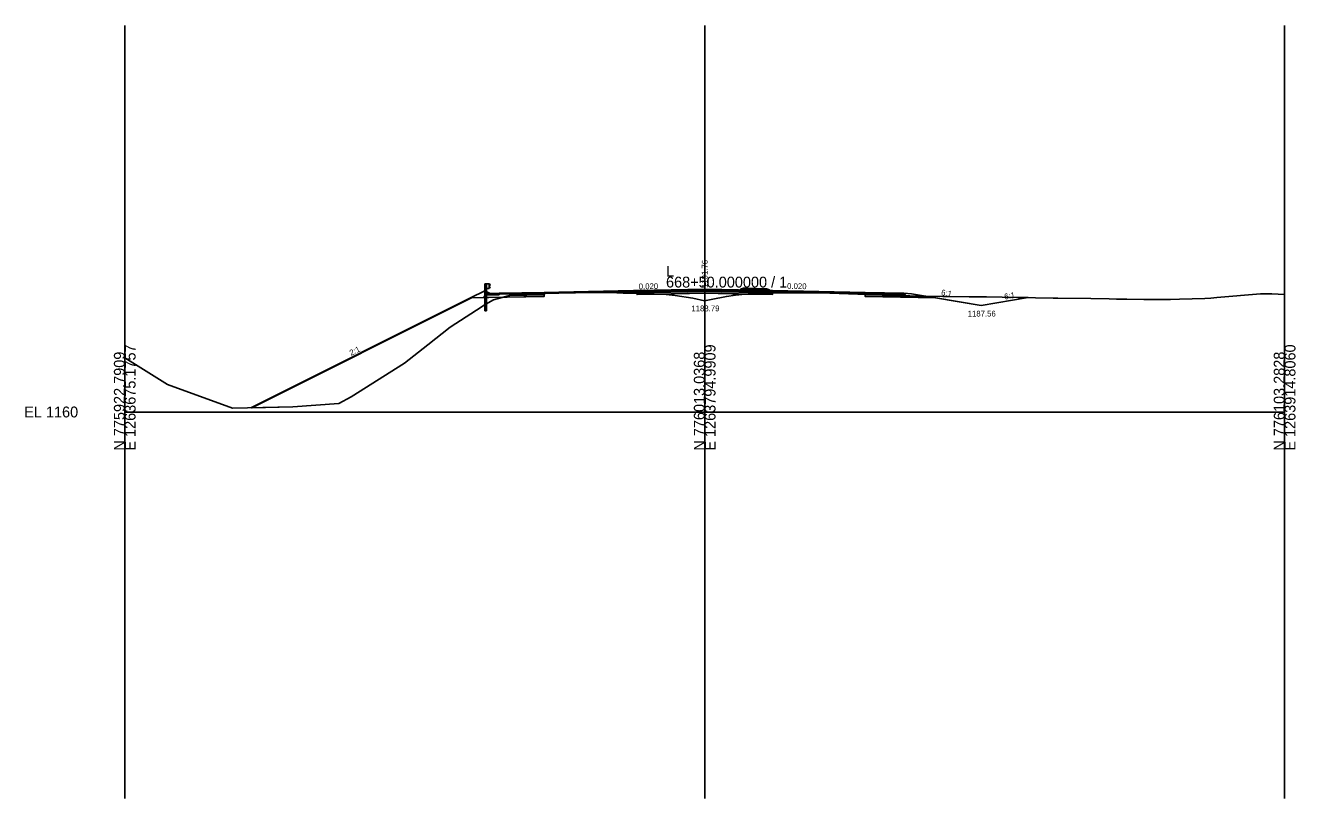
# Model space of a CAD drawing. Extents: x -41 to 1262860, y -100 to 777489.
# Drawn here: x -25.7 to 302.8, y 2655 to 2855 of the extents above; entities that cross this region are included whole.
import ezdxf

# ---------------------------------------------------------------- set-up
doc = ezdxf.new("R2010")
doc.units = 0
for name, color, linetype in [('Exist Cross Section Cell', 7, 'Continuous'), ('Exist XS Center Line Elevation Label', 7, 'Continuous'), ('Exist XS Ground Line', 7, 'Continuous'), ('Prop CMT Guardrail Graphics', 7, 'Continuous'), ('Prop CMT Pvmt Course 1', 7, 'Continuous'), ('Prop CMT Pvmt Course 4', 7, 'Continuous'), ('Prop CMT Pvmt Surface', 7, 'Continuous'), ('Prop CMT Shld Paved Course 1', 7, 'Continuous'), ('Prop CMT Shld Paved Course 2', 7, 'Continuous'), ('Prop CMT Shld Paved Course 4', 7, 'Continuous'), ('Prop CMT Slope Grass', 7, 'Continuous'), ('Prop CMT Subgrade Earthwork', 7, 'Continuous'), ('Prop Conc Curb and Gutter', 7, 'Continuous'), ('Prop Conc Island Cover', 7, 'Continuous'), ('Prop XS Ditch Standard Text', 7, 'Continuous'), ('Prop XS Earthwork Shape', 7, 'Continuous'), ('Prop XS Exc Vertical Line 1', 7, 'Continuous'), ('Prop XS Exc Vertical Line 2', 7, 'Continuous'), ('Prop XS Exc Vertical Line 3', 7, 'Continuous'), ('Prop XS Finish Grade', 7, 'Continuous'), ('Prop XS Hydro Elevations', 7, 'Continuous'), ('Prop XS SE Text', 7, 'Continuous'), ('Prop XS Side Slope Text', 7, 'Continuous'), ('Scratch_Level_4', 7, 'Continuous'), ('Scratch_Level_6', 7, 'Continuous'), ('Typical Curb CELL', 7, 'Continuous')]:
    doc.layers.add(name, color=color, linetype=linetype)

msp = doc.modelspace()

# ---------------------------------------------------------------- linework, layer by layer
at = {"layer": 'Exist Cross Section Cell'}
for p, q in [((150, 2755), (150, 2790)), ((0, 2755), (150, 2755)), ((150, 2755), (300, 2755))]:
    msp.add_line(p, q, dxfattribs=at)
at = {"layer": 'Exist XS Ground Line'}
msp.add_lwpolyline([(0, 2769.05), (11.1, 2762.1), (27.86, 2756), (43.47, 2756.32), (55.34, 2757.21), (58.55, 2758.95), (72.33, 2767.67), (78.38, 2772.37), (84.21, 2776.97), (90.99, 2781.31), (91.43, 2781.64), (92.75, 2782.52), (95.38, 2783.98), (98.24, 2784.76), (100.15, 2785.3), (103.76, 2785.44), (107.51, 2785.65), (108.83, 2785.7), (111.35, 2785.8), (120.48, 2785.88), (123.71, 2785.9), (130.82, 2785.71), (136.05, 2785.56), (138.7, 2785.46), (139.23, 2785.44), (142.37, 2785.16), (146.9, 2784.46), (149.94, 2783.78), (151.72, 2784.13), (155.64, 2784.91), (157.93, 2785.23), (161.25, 2785.6), (162.83, 2785.67), (164.85, 2785.76), (172.04, 2785.82), (177.25, 2785.86), (182.4, 2785.74), (189.6, 2785.52), (192.84, 2785.36), (194.13, 2785.3), (195.95, 2785.18), (197.83, 2785.03), (202.54, 2785.06), (203.07, 2785.05), (204.73, 2784.99), (218.4, 2784.82), (222.88, 2784.77), (231, 2784.65), (240.17, 2784.45), (240.71, 2784.44), (241.35, 2784.43), (249.91, 2784.33), (254.58, 2784.23), (256.5, 2784.15), (259.18, 2784.15), (263.55, 2784.06), (270.45, 2784.14), (272.8, 2784.19), (279.39, 2784.36), (280.89, 2784.45), (282.46, 2784.63), (293.74, 2785.53), (296.69, 2785.59), (300, 2785.41)], dxfattribs=at)
at = {"layer": 'Prop CMT Guardrail Graphics'}
for p, q in [((93.11, 2788.16), (93.59, 2788.16)), ((93.11, 2785.66), (93.11, 2788.16)), ((93.59, 2786.98), (93.59, 2788.16)), ((93.59, 2788.16), (94.26, 2788.16)), ((93.59, 2788.16), (93.59, 2785.65)), ((94.26, 2786.98), (93.59, 2786.98)), ((94.26, 2788.16), (94.26, 2786.98)), ((94.26, 2788.08), (94.26, 2787.06)), ((94.36, 2788.06), (94.26, 2788.08)), ((94.26, 2787.06), (94.36, 2787.08)), ((94.27, 2787.62), (94.5, 2787.82)), ((94.27, 2787.53), (94.27, 2787.62)), ((94.5, 2787.33), (94.27, 2787.53)), ((94.5, 2787.96), (94.36, 2788.06)), ((94.36, 2787.08), (94.5, 2787.18)), ((94.5, 2787.82), (94.5, 2787.96)), ((94.5, 2787.18), (94.5, 2787.33)), ((93.11, 2781.16), (93.11, 2785.66)), ((93.59, 2785.65), (93.59, 2781.16)), ((93.59, 2781.16), (93.11, 2781.16))]:
    msp.add_line(p, q, dxfattribs=at)
at = {"layer": 'Prop CMT Pvmt Course 1'}
for p, q in [((132.5, 2786.16), (150, 2786.51)), ((150, 2786.51), (167.49, 2786.16))]:
    msp.add_line(p, q, dxfattribs=at)
for points in [[(108.5, 2785.68), (108.5, 2785.93), (127.66, 2786.32), (127.66, 2786.32), (131.63, 2786.39), (131.63, 2786.39), (131.66, 2786.4), (131.69, 2786.4), (131.72, 2786.4), (131.75, 2786.4), (131.78, 2786.4), (131.79, 2786.4), (131.79, 2786.4), (132.5, 2786.41), (132.5, 2786.16), (132.5, 2786.16), (131.79, 2786.15), (131.79, 2786.15), (131.78, 2786.15), (131.75, 2786.15), (131.72, 2786.15), (131.69, 2786.15), (131.66, 2786.15), (131.63, 2786.14), (131.63, 2786.14), (127.66, 2786.07), (127.66, 2786.07), (108.5, 2785.68), (108.5, 2785.68)], [(191.5, 2785.68), (191.5, 2785.93), (191.5, 2785.93), (167.5, 2786.41), (167.5, 2786.16), (167.5, 2786.16), (191.5, 2785.68), (191.5, 2785.68), (191.5, 2785.68)]]:
    msp.add_lwpolyline(points, dxfattribs=at)
at = {"layer": 'Prop CMT Pvmt Course 4'}
for p, q in [((108.5, 2784.89), (93.44, 2784.59)), ((132.5, 2785.83), (132.5, 2785.37)), ((132.5, 2785.37), (150, 2785.72)), ((150, 2785.72), (167.5, 2785.37)), ((167.5, 2785.83), (167.5, 2785.37)), ((191.5, 2784.89), (202.56, 2784.67)), ((202.1, 2785.14), (202.56, 2784.67))]:
    msp.add_line(p, q, dxfattribs=at)
at = {"layer": 'Prop CMT Pvmt Surface'}
for p, q in [((108.5, 2785.93), (132.5, 2786.41)), ((132.5, 2786.41), (150, 2786.76)), ((150, 2786.76), (167.5, 2786.41)), ((167.5, 2786.41), (191.5, 2785.93)), ((96.85, 2785.7), (108.5, 2785.93)), ((191.5, 2785.93), (201.5, 2785.73))]:
    msp.add_line(p, q, dxfattribs=at)
at = {"layer": 'Prop CMT Shld Paved Course 1'}
for p, q in [((132.5, 2786.41), (150, 2786.76)), ((150, 2786.76), (167.5, 2786.41)), ((94.5, 2785.65), (108.5, 2785.93)), ((108.5, 2785.68), (96.85, 2785.45)), ((104.5, 2785.85), (104.5, 2785.85)), ((108.5, 2785.93), (108.5, 2785.68)), ((108.5, 2785.68), (108.5, 2785.68)), ((191.5, 2785.93), (191.5, 2785.68)), ((191.5, 2785.93), (201.5, 2785.73)), ((191.5, 2785.68), (191.5, 2785.68)), ((191.5, 2785.68), (201.76, 2785.48)), ((201.76, 2785.48), (201.5, 2785.73))]:
    msp.add_line(p, q, dxfattribs=at)
at = {"layer": 'Prop CMT Shld Paved Course 2'}
for p, q in [((120.48, 2785.92), (123.71, 2785.99)), ((123.71, 2785.99), (127.66, 2786.07)), ((123.71, 2785.99), (123.71, 2785.99)), ((123.71, 2785.99), (123.71, 2785.99)), ((127.66, 2786.07), (130.82, 2786.13)), ((127.66, 2786.07), (127.66, 2786.07)), ((130.82, 2786.13), (131.63, 2786.14)), ((130.82, 2786.13), (130.82, 2786.13)), ((131.63, 2786.14), (132.5, 2786.16)), ((132.5, 2785.83), (150, 2786.18)), ((132.5, 2786.16), (132.5, 2786.16)), ((132.5, 2786.16), (132.5, 2785.83)), ((150, 2786.18), (167.5, 2785.83)), ((167.5, 2785.83), (167.5, 2786.16)), ((167.5, 2786.16), (172.04, 2786.07)), ((172.04, 2786.07), (172.04, 2786.07)), ((172.04, 2786.07), (177.25, 2785.97)), ((177.25, 2785.97), (177.25, 2785.97)), ((177.25, 2785.97), (177.25, 2785.97)), ((177.25, 2785.97), (182.4, 2785.86)), ((108.5, 2785.35), (99.64, 2785.17)), ((103.9, 2785.26), (103.9, 2785.26)), ((103.9, 2785.26), (103.9, 2785.26)), ((103.9, 2785.26), (103.9, 2785.26)), ((103.9, 2785.26), (103.9, 2785.26)), ((103.9, 2785.26), (103.9, 2785.26)), ((103.9, 2785.26), (103.9, 2785.26)), ((103.9, 2785.26), (103.9, 2785.26)), ((103.9, 2785.26), (103.9, 2785.26)), ((108.5, 2785.68), (108.83, 2785.69)), ((108.83, 2785.69), (108.5, 2785.68)), ((108.5, 2785.68), (108.5, 2785.35)), ((108.5, 2785.35), (108.5, 2785.35)), ((108.83, 2785.69), (111.35, 2785.74)), ((111.35, 2785.74), (108.83, 2785.69)), ((108.83, 2785.69), (108.83, 2785.69)), ((108.83, 2785.69), (108.83, 2785.69)), ((111.35, 2785.74), (120.48, 2785.92)), ((116.62, 2785.84), (111.35, 2785.74)), ((111.35, 2785.74), (111.35, 2785.74)), ((120.48, 2785.88), (116.62, 2785.84)), ((120.48, 2785.92), (120.48, 2785.92)), ((123.71, 2785.9), (120.48, 2785.88)), ((120.48, 2785.88), (120.48, 2785.88)), ((127.66, 2785.79), (123.71, 2785.9)), ((123.71, 2785.9), (123.71, 2785.9)), ((123.71, 2785.9), (123.71, 2785.9)), ((128.94, 2785.76), (127.66, 2785.79)), ((127.66, 2785.79), (127.66, 2785.79)), ((132.5, 2785.83), (128.94, 2785.76)), ((128.94, 2785.76), (128.94, 2785.76)), ((132.5, 2785.83), (132.5, 2785.83)), ((132.5, 2785.83), (132.5, 2785.83)), ((169.01, 2785.8), (167.5, 2785.83)), ((167.5, 2785.83), (167.5, 2785.83)), ((172.04, 2785.82), (169.01, 2785.8)), ((169.01, 2785.8), (169.01, 2785.8)), ((177.25, 2785.86), (172.04, 2785.82)), ((172.04, 2785.82), (172.04, 2785.82)), ((182.4, 2785.74), (177.25, 2785.86)), ((177.25, 2785.86), (177.25, 2785.86)), ((177.25, 2785.86), (177.25, 2785.86)), ((182.4, 2785.86), (182.4, 2785.86)), ((182.4, 2785.86), (189.6, 2785.72)), ((189.6, 2785.52), (182.4, 2785.74)), ((182.4, 2785.74), (182.4, 2785.74)), ((189.6, 2785.72), (191.5, 2785.68)), ((191.5, 2785.42), (189.6, 2785.52)), ((191.5, 2785.68), (191.5, 2785.35)), ((191.5, 2785.68), (191.5, 2785.68)), ((191.5, 2785.68), (191.5, 2785.42)), ((191.5, 2785.42), (191.5, 2785.42)), ((191.5, 2785.42), (191.5, 2785.42)), ((191.5, 2785.35), (191.5, 2785.35)), ((191.5, 2785.35), (202.1, 2785.14)), ((202.1, 2785.14), (201.76, 2785.48))]:
    msp.add_line(p, q, dxfattribs=at)
at = {"layer": 'Prop CMT Shld Paved Course 4'}
for p, q in [((92.58, 2784.57), (93.32, 2785.31)), ((93.32, 2785.31), (93.83, 2785.31)), ((103.9, 2785.26), (103.9, 2785.26)), ((103.9, 2785.26), (103.9, 2785.26)), ((103.9, 2785.26), (103.9, 2785.26)), ((103.9, 2785.26), (103.9, 2785.26)), ((108.5, 2785.35), (108.5, 2784.89)), ((128.94, 2785.76), (132.5, 2785.66)), ((169.01, 2785.8), (167.5, 2785.79)), ((191.5, 2785.35), (191.5, 2784.89))]:
    msp.add_line(p, q, dxfattribs=at)
at = {"layer": 'Prop CMT Slope Grass'}
for q in [(89.47, 2784.51), (93.83, 2785.99)]:
    msp.add_line((93.14, 2786.34), q, dxfattribs=at)
at = {"layer": 'Prop CMT Subgrade Earthwork'}
for p, q in [((108.5, 2784.89), (89.47, 2784.51)), ((108.5, 2784.89), (108.5, 2785.69)), ((150, 2785.72), (132.5, 2785.37)), ((132.5, 2785.37), (132.5, 2785.66)), ((167.5, 2785.37), (150, 2785.72)), ((167.5, 2785.79), (167.5, 2785.37)), ((191.5, 2784.89), (191.5, 2785.42)), ((191.5, 2784.89), (209.78, 2784.52))]:
    msp.add_line(p, q, dxfattribs=at)
at = {"layer": 'Prop Conc Curb and Gutter'}
for p, q in [((159.25, 2786.58), (159.26, 2786.74)), ((159.25, 2786.58), (159.25, 2786.58)), ((159.25, 2786.58), (159.25, 2786.45)), ((161.01, 2786.58), (159.25, 2786.58)), ((159.25, 2786.58), (159.25, 2786.58)), ((159.25, 2786.45), (159.25, 2786.45)), ((159.25, 2786.45), (161.01, 2786.45)), ((159.26, 2786.74), (160.01, 2786.99)), ((159.26, 2786.74), (159.26, 2786.74)), ((160.01, 2786.99), (161.01, 2787.01)), ((160.01, 2786.99), (160.01, 2786.99)), ((161.01, 2787.01), (161.01, 2786.58)), ((161.01, 2786.45), (161.01, 2786.58)), ((161.01, 2786.58), (161.01, 2786.58)), ((161.01, 2786.45), (161.01, 2786.45)), ((161.01, 2786.45), (161.01, 2786.45)), ((165.99, 2786.84), (164.99, 2786.86)), ((164.99, 2786.86), (164.99, 2786.43)), ((166.75, 2786.43), (164.99, 2786.43)), ((164.99, 2786.43), (164.99, 2786.3)), ((164.99, 2786.43), (164.99, 2786.43)), ((164.99, 2786.3), (164.99, 2786.3)), ((164.99, 2786.3), (166.75, 2786.3)), ((166.74, 2786.59), (165.99, 2786.84)), ((165.99, 2786.84), (165.99, 2786.84)), ((166.75, 2786.43), (166.74, 2786.59)), ((166.74, 2786.59), (166.74, 2786.59)), ((166.75, 2786.3), (166.75, 2786.43)), ((166.75, 2786.43), (166.75, 2786.43)), ((166.75, 2786.43), (166.75, 2786.43)), ((166.75, 2786.3), (166.75, 2786.3)), ((166.75, 2786.3), (166.75, 2786.3))]:
    msp.add_line(p, q, dxfattribs=at)
at = {"layer": 'Prop Conc Island Cover'}
for p, q in [((161.01, 2787.01), (161.01, 2786.76)), ((161.01, 2787.01), (164.99, 2786.86)), ((161.01, 2786.76), (164.99, 2786.61)), ((164.99, 2786.61), (164.99, 2786.86)), ((164.99, 2786.86), (164.99, 2786.86)), ((164.99, 2786.61), (164.99, 2786.61))]:
    msp.add_line(p, q, dxfattribs=at)
at = {"layer": 'Prop XS Earthwork Shape'}
for points in [[(78.38, 2772.37), (84.21, 2776.97), (90.99, 2781.31), (91.43, 2781.64), (92.75, 2782.52), (95.38, 2783.98), (97.94, 2784.68), (93.44, 2784.59), (89.7, 2784.51), (32.87, 2756.1), (43.47, 2756.32), (55.34, 2757.21), (58.55, 2758.95), (72.33, 2767.67)], [(103.76, 2785.44), (107.51, 2785.65), (108.5, 2785.69), (108.5, 2784.89), (97.94, 2784.68), (98.24, 2784.76), (100.15, 2785.3)], [(132.5, 2785.66), (136.05, 2785.56), (138.11, 2785.48), (132.5, 2785.37)], [(146.9, 2784.46), (149.94, 2783.78), (151.72, 2784.13), (155.64, 2784.91), (157.93, 2785.23), (160.45, 2785.51), (150, 2785.72), (138.11, 2785.48), (138.7, 2785.46), (139.23, 2785.44), (142.37, 2785.16)], [(164.85, 2785.76), (167.5, 2785.79), (167.5, 2785.37), (160.45, 2785.51), (161.25, 2785.6), (162.83, 2785.67)], [(195.95, 2785.18), (197.83, 2785.03), (202.18, 2785.06), (202.56, 2784.67), (191.5, 2784.89), (191.5, 2785.42), (192.84, 2785.36), (194.13, 2785.3)], [(202.54, 2785.06), (203.07, 2785.05), (204.73, 2784.99), (207.2, 2784.96), (209.78, 2784.52), (202.56, 2784.67), (202.18, 2785.06)], [(221.5, 2782.57), (233.63, 2784.59), (231, 2784.65), (222.88, 2784.77), (218.4, 2784.82), (207.2, 2784.96), (209.78, 2784.52)]]:
    msp.add_lwpolyline(points, close=True, dxfattribs=at)
at = {"layer": 'Prop XS Exc Vertical Line 1'}
msp.add_line((0, 2655), (0, 2855), dxfattribs=at)
at = {"layer": 'Prop XS Exc Vertical Line 2'}
msp.add_line((150, 2655), (150, 2855), dxfattribs=at)
at = {"layer": 'Prop XS Exc Vertical Line 3'}
msp.add_line((300, 2655), (300, 2855), dxfattribs=at)
at = {"layer": 'Prop XS Finish Grade'}
for p, q in [((89.47, 2784.51), (32.64, 2756.09)), ((201.5, 2785.73), (203.5, 2785.57)), ((201.5, 2785.73), (202.56, 2784.67)), ((203.5, 2785.57), (221.5, 2782.57)), ((221.5, 2782.57), (233.63, 2784.59))]:
    msp.add_line(p, q, dxfattribs=at)
at = {"layer": 'Scratch_Level_4'}
msp.add_line((300, 2655), (300, 2855), dxfattribs=at)
at = {"layer": 'Scratch_Level_6'}
msp.add_line((0, 2655), (0, 2855), dxfattribs=at)
at = {"layer": 'Typical Curb CELL'}
for p, q in [((93.83, 2785.31), (93.83, 2785.99)), ((94.52, 2785.64), (93.83, 2785.99)), ((93.83, 2785.31), (96.85, 2785.28)), ((93.87, 2785.61), (94.02, 2785.65)), ((94, 2785.56), (93.87, 2785.61)), ((94.02, 2785.65), (94, 2785.56)), ((94.54, 2785.52), (94.43, 2785.45)), ((94.43, 2785.45), (94.6, 2785.41)), ((96.84, 2785.7), (94.52, 2785.64)), ((94.6, 2785.41), (94.54, 2785.52)), ((95.28, 2785.57), (95.24, 2785.46)), ((95.24, 2785.46), (95.36, 2785.45)), ((95.36, 2785.45), (95.28, 2785.57)), ((95.78, 2785.51), (95.68, 2785.43)), ((95.68, 2785.43), (95.85, 2785.39)), ((95.85, 2785.39), (95.78, 2785.51)), ((96.53, 2785.56), (96.49, 2785.44)), ((96.49, 2785.44), (96.61, 2785.44)), ((96.61, 2785.44), (96.53, 2785.56)), ((96.85, 2785.7), (96.85, 2785.7)), ((96.85, 2785.28), (96.85, 2785.69))]:
    msp.add_line(p, q, dxfattribs=at)
for centre in [(93.9, 2785.7), (93.99, 2785.42), (94.11, 2785.47), (94.37, 2785.5), (94.38, 2785.45), (94.56, 2785.36), (94.59, 2785.46), (94.78, 2785.42), (94.83, 2785.54), (94.96, 2785.51), (94.99, 2785.38), (95.05, 2785.41), (95.24, 2785.41), (95.36, 2785.46), (95.45, 2785.45), (95.55, 2785.4), (95.61, 2785.54), (95.62, 2785.49), (95.63, 2785.43), (95.84, 2785.45), (96.03, 2785.41), (96.08, 2785.52), (96.13, 2785.49), (96.21, 2785.49), (96.24, 2785.37), (96.29, 2785.4), (96.36, 2785.58), (96.72, 2785.65), (96.76, 2785.52)]:
    msp.add_circle(centre, 0.00802, dxfattribs=at)
msp.add_arc((96.84, 2785.69), 0.0104, 359.4338, 91.4818, dxfattribs=at)

# ---------------------------------------------------------------- texts
at = {"layer": 'Exist Cross Section Cell'}
for s, p in [('L', (140, 2790)), ('668+50.000000 / 1', (140, 2787.2)), ('EL 1160', (-26, 2753.6))]:
    msp.add_text(s, height=2.8, dxfattribs=at).set_placement(p)
for s, p in [('N 775922.7909', (0, 2745)), ('E 1263675.1757', (2.8, 2745)), ('N 776013.0368', (150, 2745)), ('E 1263794.9909', (152.8, 2745)), ('N 776103.2828', (300, 2745)), ('E 1263914.8060', (302.8, 2745))]:
    msp.add_text(s, height=2.8, rotation=90, dxfattribs=at).set_placement(p)
at = {"layer": 'Exist XS Center Line Elevation Label'}
msp.add_text('1188.79', height=1.5, dxfattribs=at).set_placement((146.57, 2781.04))
at = {"layer": 'Prop XS Ditch Standard Text'}
msp.add_text('1187.56', height=1.5, dxfattribs=at).set_placement((218.03, 2779.7))
at = {"layer": 'Prop XS Hydro Elevations'}
msp.add_text('1191.76', height=1.5, rotation=90, dxfattribs=at).set_placement((150.76, 2787.08))
at = {"layer": 'Prop XS SE Text'}
for rotation, p in [(1.1458, (132.96, 2786.72)), (358.8542, (171.31, 2786.86))]:
    msp.add_text('0.020', height=1.5, rotation=rotation, dxfattribs=at).set_placement(p)
at = {"layer": 'Prop XS Side Slope Text'}
for s, rotation, p in [('6:1', 350.5377, (211.08, 2785.23)), ('6:1', 9.4809, (227.62, 2784.08)), ('2:1', 26.5651, (58.57, 2769.51))]:
    msp.add_text(s, height=1.5, rotation=rotation, dxfattribs=at).set_placement(p)

doc.saveas('drawing.dxf')
